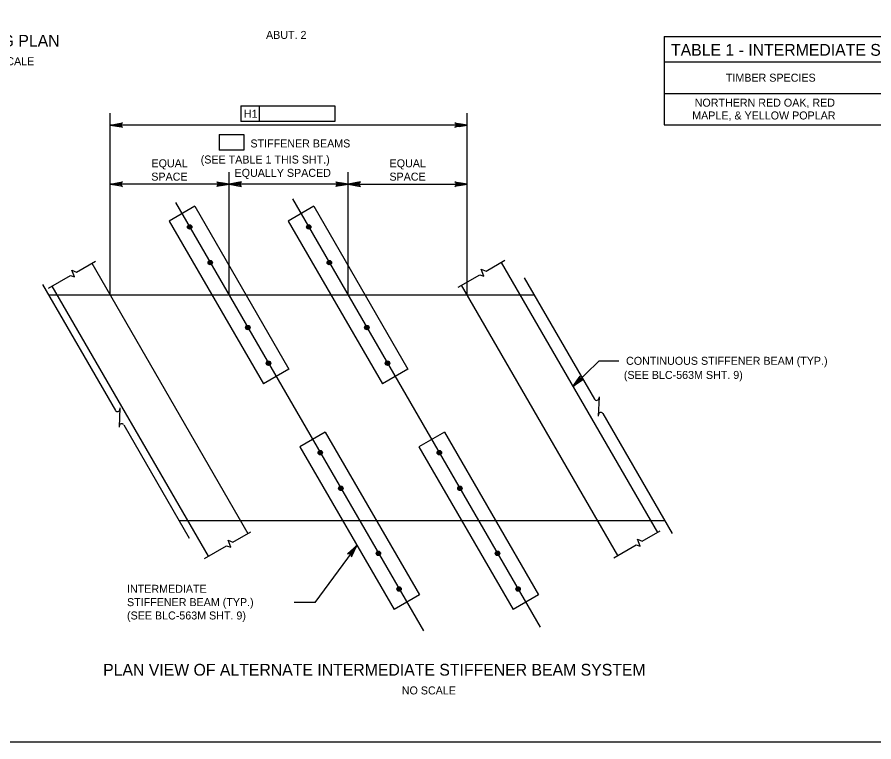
# Model space of a CAD drawing. Extents: x -8 to 75, y -110 to 0.
# Drawn here: x 46.85 to 59.7, y -65.25 to -54.37 of the extents above; entities that cross this region are included whole.
import ezdxf

# ---------------------------------------------------------------- set-up
doc = ezdxf.new("R2010")
doc.units = 0
for name, color, linetype in [('1', 7, 'Continuous'), ('2', 7, 'Continuous'), ('3', 7, 'Continuous'), ('4', 7, 'Continuous'), ('8', 7, 'Continuous')]:
    doc.layers.add(name, color=color, linetype=linetype)

msp = doc.modelspace()

# ---------------------------------------------------------------- linework, layer by layer
at = {"layer": '1'}
msp.add_lwpolyline([(35.75, -65.25), (67.25, -65.25), (67.25, -44.75), (35.75, -44.75)], close=True, dxfattribs=at)
at = {"layer": '2'}
for p, q in [((54.609, -58.544), (47.327, -58.544)), ((56.567, -61.932), (49.285, -61.932))]:
    msp.add_line(p, q, dxfattribs=at)
at = {"layer": '3'}
for p, q in [((49.517, -57.212), (49.135, -57.433)), ((49.517, -57.212), (50.929, -59.656)), ((51.302, -57.212), (50.92, -57.433)), ((51.302, -57.212), (52.715, -59.656)), ((49.135, -57.433), (50.548, -59.877)), ((50.92, -57.433), (52.333, -59.877)), ((47.746, -58.199), (48.027, -58.036)), ((47.973, -58.068), (50.316, -62.122)), ((53.886, -58.185), (54.166, -58.023)), ((54.112, -58.054), (56.456, -62.109)), ((47.715, -58.273), (47.674, -58.169)), ((47.674, -58.169), (47.746, -58.199)), ((53.854, -58.26), (53.814, -58.156)), ((53.814, -58.156), (53.886, -58.185)), ((47.326, -58.441), (47.652, -58.253)), ((47.652, -58.253), (47.715, -58.273)), ((53.466, -58.428), (53.792, -58.24)), ((53.792, -58.24), (53.854, -58.26)), ((54.46, -58.287), (55.512, -60.106)), ((47.237, -58.388), (48.327, -60.275)), ((49.723, -62.465), (47.38, -58.411)), ((55.863, -62.452), (53.519, -58.397)), ((55.58, -59.535), (55.188, -59.915)), ((50.929, -59.656), (50.548, -59.877)), ((52.715, -59.656), (52.333, -59.877)), ((55.581, -60.07), (55.57, -60.361)), ((48.396, -60.239), (48.385, -60.529)), ((55.637, -60.321), (56.679, -62.125)), ((48.452, -60.49), (49.435, -62.192)), ((51.475, -60.6), (51.093, -60.821)), ((51.475, -60.6), (52.888, -63.044)), ((53.261, -60.6), (52.879, -60.821)), ((53.261, -60.6), (54.673, -63.044)), ((51.093, -60.821), (52.506, -63.265)), ((52.879, -60.821), (54.291, -63.265)), ((50.09, -62.253), (50.357, -62.098)), ((56.229, -62.24), (56.497, -62.085)), ((49.663, -62.499), (49.996, -62.307)), ((49.996, -62.307), (50.058, -62.327)), ((50.058, -62.327), (50.018, -62.223)), ((50.018, -62.223), (50.09, -62.253)), ((55.803, -62.486), (56.136, -62.294)), ((56.136, -62.294), (56.198, -62.314)), ((56.198, -62.314), (56.157, -62.21)), ((56.157, -62.21), (56.229, -62.24)), ((52.888, -63.044), (52.506, -63.265)), ((54.673, -63.044), (54.291, -63.265))]:
    msp.add_line(p, q, dxfattribs=at)
msp.add_lwpolyline([(55.188, -59.915), (55.297, -59.761), (55.294, -59.778), (55.297, -59.792), (55.304, -59.802), (55.315, -59.81), (55.329, -59.813), (55.346, -59.811), (55.188, -59.915), (55.329, -59.813), (55.315, -59.81), (55.188, -59.915), (55.304, -59.802), (55.297, -59.792), (55.188, -59.915), (55.294, -59.778)], dxfattribs=at)
for centre, radius in [((49.441, -57.522), 0.0333), ((49.441, -57.522), 0.0295), ((49.441, -57.522), 0.025), ((49.441, -57.522), 0.0167), ((49.441, -57.522), 0.00833), ((51.227, -57.522), 0.0333), ((51.227, -57.522), 0.0295), ((51.227, -57.522), 0.025), ((51.227, -57.522), 0.0167), ((51.227, -57.522), 0.00833), ((49.75, -58.057), 0.0333), ((49.75, -58.057), 0.0295), ((49.75, -58.057), 0.025), ((49.75, -58.057), 0.0167), ((49.75, -58.057), 0.00833), ((51.536, -58.057), 0.0333), ((51.536, -58.057), 0.0295), ((51.536, -58.057), 0.025), ((51.536, -58.057), 0.0167), ((51.536, -58.057), 0.00833), ((50.314, -59.032), 0.0333), ((50.314, -59.032), 0.0295), ((50.314, -59.032), 0.025), ((50.314, -59.032), 0.0167), ((50.314, -59.032), 0.00833), ((52.099, -59.032), 0.0333), ((52.099, -59.032), 0.0295), ((52.099, -59.032), 0.025), ((52.099, -59.032), 0.0167), ((52.099, -59.032), 0.00833), ((50.623, -59.567), 0.0333), ((50.623, -59.567), 0.0295), ((50.623, -59.567), 0.025), ((50.623, -59.567), 0.0167), ((50.623, -59.567), 0.00833), ((52.409, -59.567), 0.0333), ((52.409, -59.567), 0.0295), ((52.409, -59.567), 0.025), ((52.409, -59.567), 0.0167), ((52.409, -59.567), 0.00833), ((51.4, -60.91), 0.0333), ((51.4, -60.91), 0.0295), ((51.4, -60.91), 0.025), ((51.4, -60.91), 0.0167), ((53.185, -60.91), 0.0333), ((53.185, -60.91), 0.0295), ((53.185, -60.91), 0.025), ((53.185, -60.91), 0.0167), ((51.4, -60.91), 0.00833), ((53.185, -60.91), 0.00833), ((51.709, -61.445), 0.0333), ((53.494, -61.445), 0.0333), ((51.709, -61.445), 0.0295), ((51.709, -61.445), 0.025), ((51.709, -61.445), 0.0167), ((51.709, -61.445), 0.00833), ((53.494, -61.445), 0.0295), ((53.494, -61.445), 0.025), ((53.494, -61.445), 0.0167), ((53.494, -61.445), 0.00833), ((52.272, -62.42), 0.0333), ((52.272, -62.42), 0.0295), ((52.272, -62.42), 0.025), ((52.272, -62.42), 0.0167), ((52.272, -62.42), 0.00833), ((54.058, -62.42), 0.0333), ((54.058, -62.42), 0.0295), ((54.058, -62.42), 0.025), ((54.058, -62.42), 0.0167), ((54.058, -62.42), 0.00833), ((52.582, -62.955), 0.0333), ((52.582, -62.955), 0.0295), ((52.582, -62.955), 0.025), ((52.582, -62.955), 0.0167), ((52.582, -62.955), 0.00833), ((54.367, -62.955), 0.0333), ((54.367, -62.955), 0.0295), ((54.367, -62.955), 0.025), ((54.367, -62.955), 0.0167), ((54.367, -62.955), 0.00833)]:
    msp.add_circle(centre, radius, dxfattribs=at)
for centre, start, end in [((55.544, -60.088), 210.0292, 0.0292), ((48.359, -60.257), 210.0292, 0.0292), ((55.607, -60.342), 35.3578, 177.8964), ((48.422, -60.511), 35.3578, 177.8964)]:
    msp.add_arc(centre, 0.0364, start, end, dxfattribs=at)
at = {"layer": '4'}
for p, q in [((50.208, -55.703), (50.208, -55.939)), ((50.208, -55.703), (51.62, -55.703)), ((50.484, -55.703), (50.484, -55.939)), ((51.62, -55.703), (51.62, -55.939)), ((48.248, -58.544), (48.248, -55.812)), ((53.604, -58.544), (53.604, -55.812)), ((53.604, -55.992), (48.248, -55.992)), ((51.62, -55.939), (50.208, -55.939)), ((49.885, -56.136), (50.256, -56.136)), ((49.885, -56.136), (49.885, -56.372)), ((50.256, -56.136), (50.256, -56.372)), ((50.256, -56.372), (49.885, -56.372)), ((48.248, -58.544), (48.248, -56.698)), ((50.033, -58.544), (50.033, -56.698)), ((51.819, -58.544), (51.819, -56.698)), ((53.604, -58.544), (53.604, -56.698)), ((49.913, -56.878), (48.248, -56.878)), ((51.699, -56.878), (50.153, -56.878)), ((51.939, -56.878), (53.604, -56.878)), ((49.231, -57.156), (52.947, -63.585)), ((50.984, -57.1), (54.7, -63.529)), ((55.879, -59.535), (55.58, -59.535)), ((51.322, -63.159), (51.008, -63.159))]:
    msp.add_line(p, q, dxfattribs=at)
for points in [[(48.248, -55.992), (48.434, -55.957), (48.42, -55.967), (48.412, -55.979), (48.41, -55.992), (48.412, -56.004), (48.42, -56.017), (48.434, -56.027), (48.248, -55.992), (48.42, -56.017), (48.412, -56.004), (48.248, -55.992), (48.41, -55.992), (48.412, -55.979), (48.248, -55.992), (48.42, -55.967)], [(53.604, -55.992), (53.418, -56.027), (53.432, -56.017), (53.439, -56.004), (53.441, -55.992), (53.439, -55.979), (53.432, -55.967), (53.418, -55.957), (53.604, -55.992), (53.432, -55.967), (53.439, -55.979), (53.604, -55.992), (53.441, -55.992), (53.439, -56.004), (53.604, -55.992), (53.432, -56.017)], [(48.248, -56.878), (48.434, -56.843), (48.42, -56.853), (48.412, -56.865), (48.41, -56.878), (48.412, -56.89), (48.42, -56.903), (48.434, -56.913), (48.248, -56.878), (48.42, -56.903), (48.412, -56.89), (48.248, -56.878), (48.41, -56.878), (48.412, -56.865), (48.248, -56.878), (48.42, -56.853)], [(50.033, -56.878), (49.847, -56.913), (49.861, -56.903), (49.868, -56.89), (49.871, -56.878), (49.868, -56.865), (49.861, -56.853), (49.847, -56.843), (50.033, -56.878), (49.861, -56.853), (49.868, -56.865), (50.033, -56.878), (49.871, -56.878), (49.868, -56.89), (50.033, -56.878), (49.861, -56.903)], [(50.033, -56.878), (50.22, -56.913), (50.205, -56.903), (50.198, -56.89), (50.196, -56.878), (50.198, -56.865), (50.205, -56.853), (50.22, -56.843), (50.033, -56.878), (50.205, -56.853), (50.198, -56.865), (50.033, -56.878), (50.196, -56.878), (50.198, -56.89), (50.033, -56.878), (50.205, -56.903)], [(51.819, -56.878), (51.632, -56.913), (51.646, -56.903), (51.654, -56.89), (51.656, -56.878), (51.654, -56.865), (51.646, -56.853), (51.632, -56.843), (51.819, -56.878), (51.646, -56.853), (51.654, -56.865), (51.819, -56.878), (51.656, -56.878), (51.654, -56.89), (51.819, -56.878), (51.646, -56.903)], [(51.819, -56.878), (52.005, -56.913), (51.991, -56.903), (51.983, -56.89), (51.981, -56.878), (51.983, -56.865), (51.991, -56.853), (52.005, -56.843), (51.819, -56.878), (51.991, -56.853), (51.983, -56.865), (51.819, -56.878), (51.981, -56.878), (51.983, -56.89), (51.819, -56.878), (51.991, -56.903)], [(53.604, -56.878), (53.418, -56.913), (53.432, -56.903), (53.439, -56.89), (53.441, -56.878), (53.439, -56.865), (53.432, -56.853), (53.418, -56.843), (53.604, -56.878), (53.432, -56.853), (53.439, -56.865), (53.604, -56.878), (53.441, -56.878), (53.439, -56.89), (53.604, -56.878), (53.432, -56.903)], [(51.949, -62.301), (51.318, -63.16)], [(51.949, -62.301), (51.81, -62.43), (51.827, -62.425), (51.841, -62.426), (51.852, -62.432), (51.861, -62.441), (51.867, -62.454), (51.867, -62.472), (51.949, -62.301), (51.867, -62.454), (51.861, -62.441), (51.949, -62.301), (51.852, -62.432), (51.841, -62.426), (51.949, -62.301), (51.827, -62.425)]]:
    msp.add_lwpolyline(points, dxfattribs=at)
for points in [[(48.368, -55.972), (48.368, -56.012), (48.248, -55.992)], [(53.484, -55.972), (53.484, -56.012), (53.604, -55.992)], [(48.368, -56.858), (48.368, -56.898), (48.248, -56.878)], [(49.913, -56.858), (49.913, -56.898), (50.033, -56.878)], [(50.153, -56.858), (50.153, -56.898), (50.033, -56.878)], [(51.699, -56.858), (51.699, -56.898), (51.819, -56.878)], [(51.939, -56.858), (51.939, -56.898), (51.819, -56.878)], [(53.484, -56.858), (53.484, -56.898), (53.604, -56.878)], [(51.949, -62.301), (51.886, -62.403), (51.87, -62.392)]]:
    msp.add_lwpolyline(points, close=True, dxfattribs=at)
at = {"layer": '8'}
for p, q in [((56.557, -54.664), (65.445, -54.664)), ((56.557, -54.664), (56.557, -55.991)), ((56.557, -55.046), (65.445, -55.046)), ((56.557, -55.518), (65.445, -55.518)), ((56.557, -55.991), (65.445, -55.991))]:
    msp.add_line(p, q, dxfattribs=at)

# ---------------------------------------------------------------- texts
at = {"layer": '4'}
for s, height, p in [('ABUT. 2', 0.12, (50.587, -54.7)), ('FRAMING PLAN', 0.17717, (45.714, -54.816)), ('TABLE 1 - INTERMEDIATE STIFFENER BEAM DESIGN DATA', 0.17717, (56.66, -54.953)), ('NO SCALE', 0.12, (46.3, -55.095)), ('TIMBER SPECIES', 0.12, (57.483, -55.342)), ('NORTHERN RED OAK, RED', 0.12, (57.015, -55.717)), ('H1', 0.12, (50.255, -55.884)), ('MAPLE, & YELLOW POPLAR', 0.12, (56.978, -55.909)), ('STIFFENER BEAMS', 0.12, (50.353, -56.329)), ('EQUAL', 0.12, (48.869, -56.627)), ('(SEE TABLE 1 THIS SHT.)', 0.12, (49.607, -56.57)), ('EQUAL', 0.12, (52.44, -56.627)), ('EQUALLY SPACED', 0.12, (50.115, -56.77)), ('SPACE', 0.12, (48.866, -56.827)), ('SPACE', 0.12, (52.437, -56.827)), ('CONTINUOUS STIFFENER BEAM (TYP.)', 0.12, (55.986, -59.591)), ('(SEE BLC-563M SHT. 9)', 0.12, (55.953, -59.803)), ('INTERMEDIATE', 0.12, (48.502, -63.013)), ('STIFFENER BEAM (TYP.)', 0.12, (48.502, -63.213)), ('(SEE BLC-563M SHT. 9)', 0.12, (48.502, -63.413)), ('PLAN VIEW OF ALTERNATE INTERMEDIATE STIFFENER BEAM SYSTEM', 0.17717, (48.144, -64.256)), ('NO SCALE', 0.12, (52.623, -64.538))]:
    msp.add_text(s, height=height, dxfattribs=at).set_placement(p)

doc.saveas('drawing.dxf')
